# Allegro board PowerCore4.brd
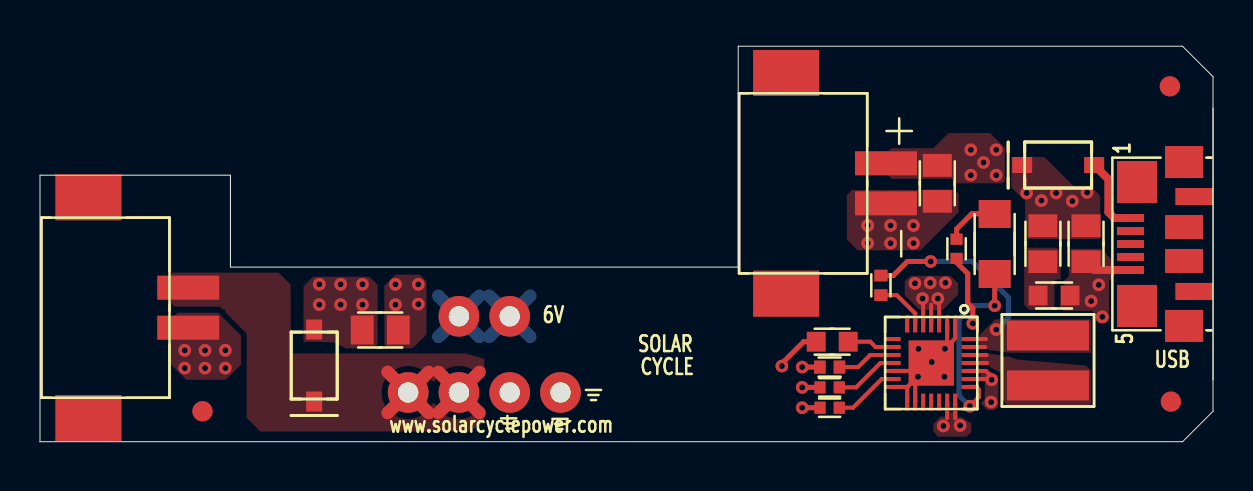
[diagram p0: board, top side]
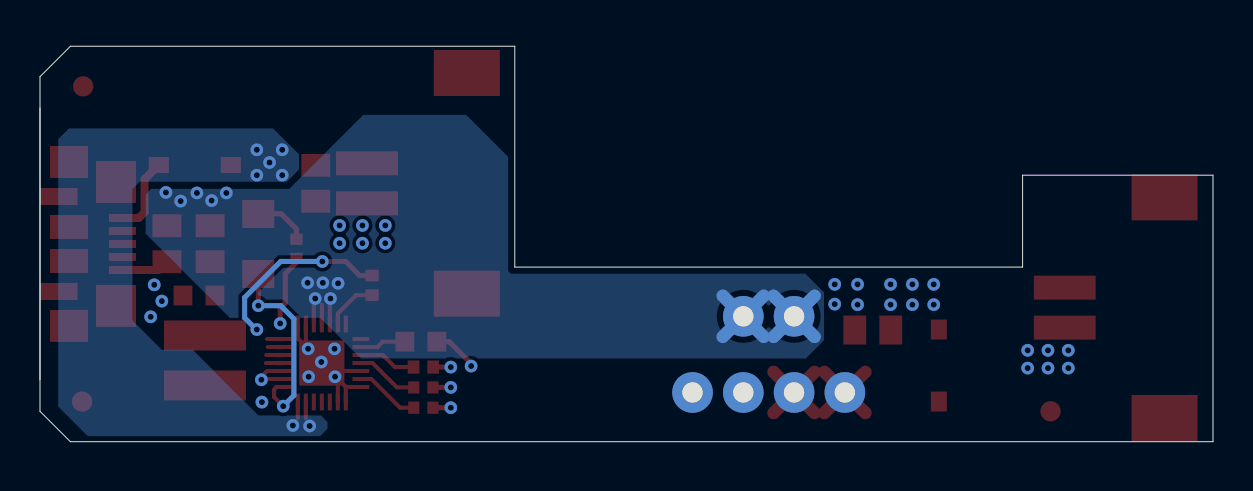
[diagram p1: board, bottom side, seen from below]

Outline 58.67 x 19.79 mm; copper layers: TOP, LAYER2_GND, LAYER3_PWR, BOTTOM. Coordinates in mm from the lower left corner of the outline.
Outline path: 0,13.34 9.53,13.34 9.53,8.74 34.92,8.74 34.92,19.79 57.15,19.79 58.67,18.26 58.67,1.52 57.15,0 0,0 0,13.34

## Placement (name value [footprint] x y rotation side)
BATTERY  -  [DF3DZ_2P_2H]  42.32 12.93 90 top
C1  2.2uF  [CAPC2013X145AN]  52.32 9.91 90 top
C3A  10uF  [CAPC2013X145AN]  44.88 12.93 270 top
C4  22uF  [CAPC2013X145AN]  17.02 5.59 0 top
C5  -  [CAPC1005X60N]  39.5 3.73 180 top
C6  -  [CAPC1608X95N]  39.62 5 180 top
C7  -  [CAPC1005X60N]  42.06 7.82 90 top
C10  4.7uF  [CAPC2013X145AN]  50.16 9.91 90 top
GND2  -  [2HOLE]  23.5 2.46 0 top
IN6V  -  [ZX62R-B-5P]  54.53 9.89 90 top
IN6V2  -  [2HOLE]  20.95 6.27 0 top
L1  -  [DEA401XCK]  50.42 4.06 90 top
LED  -  [DSAH3780]  47.75 9.89 90 top
NOREF  -  [unnamed]  8.13 1.52 0 top
NOREF#2  -  [unnamed]  56.52 17.78 0 top
NOREF#3  -  [#2]  0 0 0 top
NOREF#4  -  [#2]  9.53 13.34 0 top
NOREF#5  -  [#2]  0 13.34 0 top
NOREF#6  -  [#2]  34.92 19.79 0 top
NOREF#7  -  [#2]  0 0 0 top
NOREF#8  -  [unnamed]  56.57 2.01 0 top
NOREF#9  -  [#2]  -317.04 -262.41 0 top
NOREF#10  -  [#2]  58.67 1.52 0 top
NOREF#11  -  [#2]  57.97 18.97 0 top
NOREF#12  -  [#2]  57.15 19.79 0 top
NOREF#13  -  [#2]  32.69 -71.68 0 top
NOREF#14  -  [#2]  521.16 -249.71 0 top
NOREF#15  -  [#2]  34.92 8.74 0 top
R3  2.2K  [RESC1005X40]  45.85 9.65 270 top
R7  3.01K  [RESC1005X40]  39.5 2.72 0 top
R11  604  [RESC1005X40]  39.5 1.7 0 top
R15  -  [RESC1608X50AN]  50.72 7.32 180 top
SD1  -  [PMEG3020ER]  13.72 3.81 90 top
SD2  -  [PMEG3020ER]  50.93 13.84 0 top
SYSOUT  -  [DF3DZ_2P_2H]  7.42 6.71 90 top
SYSOUT2  -  [2HOLE]  18.41 2.46 0 top
U1  -  [QFN40P400X400X80-29AN]  44.58 3.94 270 top

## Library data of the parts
BATTERY SYSOUT = DF3DZ_2P_2H
C1 C3A C4 C10 = C0805
C5 C7 = C0402
C6 = C0603
GND2 IN6V2 SYSOUT2 = 2HOLE
IN6V = ZX62R-B-5P
L1 = DEA401XCK
LED = APL3015ZGC
R3 R7 R11 = R0402
R15 = R0603
SD1 SD2 = SCHOTTKY
U1 = MAX8903G

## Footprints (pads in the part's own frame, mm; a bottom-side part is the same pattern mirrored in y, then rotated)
2HOLE
  round 2.032 hole 1.016: 1(0,0) 2(2.54,0)
CAPC1005X60N
  rect 0.584x0.66 smd: 1(-0.49,0) 2(0.49,0)
CAPC1608X95N
  rect 0.94x0.991 smd: 1(-0.8,0) 2(0.8,0)
CAPC2013X145AN
  rect 1.143x1.448 smd: 1(-0.899,0) 2(0.899,0)
DEA401XCK
  rect 1.501x4.1 smd: 1(1.25,0) 2(-1.25,0)
DF3DZ_2P_2H
  rect 2.301x3.299 smd: (-5.522,4.994) (5.522,4.994)
  rect 1.199x3.099 smd: 1(1.001,0) 2(-1.001,0)
DSAH3780
  rect 1.4x1.6 smd: 1(-1.501,0) 2(1.501,0)
PMEG3020ER
  rect 1.001x0.8 smd: 1(1.801,0) 2(-1.801,0)
QFN40P400X400X80-29AN
  rect 0.838x0.203 smd: 1(-1.951,1.199) 2(-1.951,0.8) 3(-1.951,0.399) 4(-1.951,0) 5(-1.951,-0.399) 6(-1.951,-0.8) 7(-1.951,-1.199) 15(1.951,-1.199) 16(1.951,-0.8) 17(1.951,-0.399) 18(1.951,0) 19(1.951,0.399) 20(1.951,0.8) 21(1.951,1.199)
  rect 0.203x0.838 smd: 8(-1.199,-1.951) 9(-0.8,-1.951) 10(-0.399,-1.951) 11(0,-1.951) 12(0.399,-1.951) 13(0.8,-1.951) 14(1.199,-1.951) 22(1.199,1.951) 23(0.8,1.951) 24(0.399,1.951) 25(0,1.951) 26(-0.399,1.951) 27(-0.8,1.951) 28(-1.199,1.951)
  rect 2.261x2.261 smd: 29(0,0)
RESC1005X40
  rect 0.559x0.61 smd: 1(-0.48,0) 2(0.48,0)
RESC1608X50AN
  rect 0.94x0.991 smd: 1(-0.8,0) 2(0.8,0)
unnamed
  round 1.016 smd: (0,0)
ZX62R-B-5P
  rect 1.6x1.9 smd: (-4.1,-2.695) (4.1,-2.695)
  rect 2.101x1.999 smd: (-3.099,-0.345) (3.099,-0.345)
  rect 0.851x1.88 smd: (-2.375,-3.205) (2.375,-3.205)
  rect 1.199x1.9 smd: (-0.851,-2.695) (0.851,-2.695)
  rect 0.399x1.349 smd: 1(1.3,-0.02) 2(0.65,-0.02) 3(0,-0.02) 4(-0.65,-0.02) 5(-1.3,-0.02)

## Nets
GND2: BATTERY.2 C1.1 C3A.2 C4.2 C5.2 C6.2 GND2.1(TP-1) GND2.2(TP-1) IN6V.5(TP-5) R7.1 R11.1 R15.1 SYSOUT.2 U1.1 U1.2 U1.12 U1.14 U1.15 U1.16 U1.29
BAT: BATTERY.1 C3A.1 U1.20 U1.21
BST: C7.1 U1.6
CHG: LED.1 U1.22
CS: L1.2 U1.25 U1.26
CT: C5.1 U1.10
IDC: R7.2 U1.11
IN6V: IN6V.1(TP-1) SD2.1(TP-1)
IN6V2: C1.2 C10.2 IN6V2.1(TP-1) IN6V2.2(TP-1) SD2.2(TP-2) U1.3 U1.4 U1.5
ISET: R11.2 U1.13
LX: C7.2 L1.1 U1.27 U1.28
N0001: C10.1 R15.2
N0002: LED.2 R3.1
SYS: C4.1 R3.2 SD1.1(TP-1) U1.23 U1.24
SYSOUT2: SD1.2(TP-2) SYSOUT.1 SYSOUT2.1(TP-1) SYSOUT2.2(TP-1)
VL: C6.1 U1.9

Pads without a net: IN6V 2 3 4; U1 7 8 17 18 19

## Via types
v1: diameter 0.635, hole 0.305, TOP to BOTTOM, 58 vias

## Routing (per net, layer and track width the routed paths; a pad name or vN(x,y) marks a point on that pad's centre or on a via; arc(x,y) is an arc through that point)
GND2: length 28.4
  TOP w0.203: v1(43.92,3.25) 43.63,3.54 U1.12 ; U1.15 43.38,2.74 ; 43.38,2.74 43.78,3.14 ; 43.38,2.74 U1.14 ; U1.1 45.78,5.16 v1(45.26,4.65) ; U1.2 45.38,4.74 U1.29 43.78,3.14 ; 43.78,3.14 U1.16
  TOP w0.254: R7.1 v1(38.13,2.72) ; 52.74,8.59 C1.1 ; C6.2 38.2,5 37.11,3.91 v1(37.11,3.78) ; C5.2 v1(38.13,3.73) ; R11.1 v1(38.13,1.7)
  TOP w0.399: IN6V.5 52.74,8.59
  LAYER2_GND w0.635: 22.47,3.49 GND2.1 ; GND2.1 22.47,1.44 ; GND2.1 24.52,1.44 ; GND2.1 24.52,3.49 ; 25.01,3.49 GND2.2 ; GND2.2 27.06,3.49 ; GND2.2 25.01,1.44 ; GND2.2 27.06,1.44
  vias: v1(7.24,4.57) v1(7.24,3.68) v1(8.26,4.57) v1(8.26,3.68) v1(9.27,4.57) v1(9.27,3.68) v1(17.78,7.87) v1(17.78,6.86) v1(18.92,7.87) v1(18.92,6.88) v1(41.4,10.82) v1(41.4,9.93) v1(42.55,10.82) v1(42.55,9.93) v1(43.69,10.82) v1(43.69,9.93) v1(43.94,4.65) v1(44.6,3.99) v1(45.24,3.25) v1(52.58,7.04) v1(52.96,7.85) v1(53.14,6.25)
BAT: length 1.6
  TOP w0.203: U1.21 45.78,1.17 ; U1.20 45.38,1.18
  vias: v1(45.19,0.79) v1(46.02,0.81) v1(46.56,14.61) v1(46.56,13.34) v1(47.19,13.97) v1(47.83,14.61) v1(47.83,13.34)
BST: length 2.6
  TOP w0.203: U1.6 43.78,6.41 42.86,7.33 C7.1
CHG: length 9.7
  TOP w0.203: U1.22 46.84,2.74 46.96,2.61 46.96,2.24 v1(46.51,1.78)
  TOP w0.254: LED.1 v1(47.75,6.81)
  BOTTOM w0.254: v1(46.51,1.78) 45.97,2.31 45.97,6.15 46.63,6.81 v1(47.75,6.81)
CS: length 1.7
  TOP w0.203: U1.26 47.35,4.34 ; U1.25 47.37,3.94
CT: length 2.9
  TOP w0.203: U1.10 41.52,4.34 40.92,3.73 C5.1
IDC: length 3.2
  TOP w0.203: U1.11 42.04,3.94 40.82,2.72 R7.2
IN6V: length 3.9
  TOP w0.399: IN6V.1 53.73,11.19 53.44,11.48 53.44,13.13 SD2.1
IN6V2: length 14.5
  TOP w0.203: U1.3 44.98,6.87 ; U1.4 44.58,6.86 ; U1.5 44.18,6.82
  BOTTOM w0.635: 19.93,7.3 IN6V2.1 ; IN6V2.1 21.98,5.25 ; IN6V2.1 21.98,7.3 ; IN6V2.1 19.93,5.25 ; 22.47,5.25 23.5,6.27 ; 23.5,6.27 24.52,7.3 ; 23.5,6.27 22.47,7.3 ; 23.5,6.27 24.52,5.25
  vias: v1(43.76,7.92) v1(44.15,7.16) v1(44.53,7.95) v1(44.91,7.16) v1(45.29,7.95) v1(49.35,12.45) v1(50.09,12.06) v1(50.83,12.45) v1(51.64,12.04) v1(52.37,12.47)
ISET: length 3.2
  TOP w0.203: R11.2 40.67,1.7 42.1,3.14 U1.13
LX: length 10.8
  TOP w0.203: U1.27 47.28,4.74 ; U1.28 47.32,5.14
  TOP w0.254: v1(44.55,9.02) 43.38,9.02 42.68,8.31 C7.2
  BOTTOM w0.254: v1(47.83,5.61) 47.85,5.61 48.44,6.2 48.44,7.21 46.63,9.02 v1(44.55,9.02)
N0002: length 2.7
  TOP w0.254: R3.1 45.85,10.64 46.61,11.4 47.74,11.4 LED.2
SYS: length 6.1
  TOP w0.203: U1.24 47.31,3.54 47.68,3.17 47.64,3.14 U1.23
  TOP w0.254: v1(46.66,5.92) 46.66,6.68 46.41,6.93 46.41,8.41 45.85,8.97 R3.2
  vias: v1(13.97,7.87) v1(13.97,6.86) v1(15.04,7.87) v1(15.04,6.86) v1(16.13,7.87) v1(16.13,6.86) v1(47.6,3.1) v1(47.57,1.98)
SYSOUT2: length 11.6
  TOP w0.635: SYSOUT2.2 21.98,3.49 ; SYSOUT2.2 19.93,1.44 ; SYSOUT2.2 19.93,3.49 ; SYSOUT2.2 21.98,1.44 ; SYSOUT2.1 19.44,3.49 ; SYSOUT2.1 17.39,3.49 ; SYSOUT2.1 17.39,1.44 ; SYSOUT2.1 19.44,1.44
VL: length 2.3
  TOP w0.203: C6.1 41.53,5 41.8,4.74 U1.9

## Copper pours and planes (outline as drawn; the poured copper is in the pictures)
GND2 on TOP: 51.59,9.65 51.46,9.53 51.46,8.28 50.95,7.77 50.95,6.78 51.18,6.55 52.6,6.55 52.81,6.35 52.81,6.07 52.96,5.92 53.31,5.92 53.47,6.07 53.47,8.05 53.82,8.41 54.81,8.41 54.81,8.79 53.82,8.79 53.82,8.89 53.06,9.65
GND2 on TOP: 17.42,4.67 18.64,4.67 19.33,5.36 19.33,8.03 19,8.36 17.78,8.36 17.22,7.8 17.22,4.88
GND2 on TOP: 45.75,12.6 45.95,12.4 45.95,11.48 44.04,9.58 40.89,9.58 40.36,10.11 40.36,12.34 40.61,12.6
GND2 on TOP: 8.92,6.45 6.88,6.45 6.53,6.1 6.53,3.89 7.32,3.1 9.3,3.1 10.06,3.86 10.06,5.31
GND2 on LAYER2_GND: 57.03,0.28 0.28,0.28 0.28,13.06 9.25,13.06 9.25,8.46 35.2,8.46 35.2,19.51 57.03,19.51 58.39,18.15 58.39,1.64
BAT on TOP: 45.24,1.24 45.03,1.24 44.68,0.89 44.68,0.56 44.89,0.25 46.35,0.25 46.58,0.48 46.58,0.93 46.05,1.24 45.92,1.24 45.9,1.47 45.24,1.47
BAT on TOP: 42.57,14.68 44.68,14.68 45.44,15.44 47.52,15.44 48.26,14.71 48.26,13.06 48.13,12.93 45.82,12.93 45.59,13.16 42.6,13.16 42.24,13.51 42.24,14.35
BAT on BOTTOM: 44.65,0.28 44.3,0.64 44.3,0.99 44.63,1.32 47.75,1.32 51.03,4.6 52.58,4.6 54.05,6.07 54.05,12.65 53.72,12.98 53.75,13 46.33,13 45.72,13.61 45.72,14.38 47.02,15.67 57.23,15.67 57.76,15.14 57.76,1.75 56.29,0.28
CS on TOP: 46.99,4.47 48.02,4.47 48.84,4.11 52.32,3.81 52.58,3.56 52.58,1.91 52.45,1.78 48.39,1.78 48.13,2.12 48.13,3.4 47.37,3.81 46.99,3.81
IN6V2 on TOP: 53.04,10.14 53.01,10.13 49.35,10.13 49.28,10.21 49.28,12.04 48.59,12.73 48.59,14.25 50.24,14.25 51.69,12.8 52.53,12.8 53.04,12.29
IN6V2 on TOP: 45.16,6.6 45.92,7.37 45.92,7.92 45.54,8.31 43.54,8.31 43.26,8.03 43.26,7.26 43.92,6.6
IN6V2 on BOTTOM: 42.62,4.17 20.37,4.17 19.46,5.08 19.46,7.47 20.4,8.41 35.13,8.41 35.26,8.53 35.26,14.25 37.36,16.36 42.49,16.36 46.2,12.65 53.11,12.65 53.39,12.37 53.39,10.41 49.17,6.2 44.65,6.2
LX on TOP: 46.99,5.33 47.78,6.12 52.53,6.12 52.58,6.07 52.58,4.45 48.51,4.45 47.42,4.6 46.99,4.6
N0001 on TOP: 49.38,9.7 50.85,9.7 51.05,9.5 51.05,7.09 50.57,6.6 49.48,6.6 49.23,6.86 49.23,9.55
SYS on TOP: 13.18,5 13.18,7.77 13.67,8.26 16.48,8.26 16.89,7.85 16.89,4.9 16.71,4.67 15.29,4.67 14.68,4.98
SYS on TOP: 47.04,1.93 47.4,1.57 47.73,1.57 47.93,1.72 47.93,3.51 47.73,3.71 47.04,3.71
SYS on LAYER3_PWR: 46.58,6.68 48.56,4.7 48.56,1.24 47.68,0.36 12.6,0.36 11.79,1.17 11.79,7.87 12.19,8.28 42.57,8.28 44.17,6.68
SYSOUT2 on TOP: 21.26,4.42 22.23,4.15 22.23,0.99 21.46,0.51 11.02,0.51 10.34,1.19 10.34,5.41 8.99,6.76 6.73,6.76 6.27,7.21 6.27,8.13 6.6,8.46 11.94,8.46 12.54,7.86 12.55,4.42

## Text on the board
BOTTOM: SOLDER SIDE ETCH | 4
Ref Des/Silkscreen Bottom: BOTTOM SILKSCREEN | 4
User.Comments: SOLARCYCLE
Ref Des/Silkscreen Top: www.solarcyclepower.com | 6V | SOLAR | CYCLE | USB | TOP SILKSCREEN | 5
LAYER2_GND: LAYER 2 GND PLANE | 2
LAYER3_PWR: LAYER 3 GND PLANE | 3
BODY_CENTER: (408) 582-2787  johnc@cdspcb.com | CORCORAN DESIGN SERVICE,INC | SOLARCYCLE
DISPLAY_TOP: PASTEMASK BOTTOM | 10
User.11: NOTES (UNLESS OTHERWISE SPECIFIED): | SOLDERED ENTITY. | 4.   SOLDER MASK BOTH SIDES WITH LIQUID PHOTO IMAGEABLE SOLDER MASK (LPI), GREEN. | 5.   SILKSCREEN TOP SIDE WITH WHITE EPOXY NON CONDUCTIVE INK.  SILKSCREEN MAY BE TRIMMED OFF ANY | 2.   NUMBER OF LAYERS: 4 | 3.   FINISH: HOT AIR SOLDER LEVELED (HASL) | 1.   MATERIAL : FR-4 | 2X | NOTE: NOMINAL THICKNESS = 40 MILS (+/-10%) | STACKUP | DETAIL `A'
User.12: NOTES (UNLESS OTHERWISE SPECIFIED): | 1.  Workmanship standards and acceptability criteria shall meet | IPC-A-610 (latest revision). | 10/1 | SYSOUT2 | IN6V2 | GND2 | L1 | C4 | COMPONENT SIDE | C5 | R7 | R11 | C7 | C6 | U1 | R3 | C10 | R15 | SD2 | C1 | SYSOUT | BATTERY | SD1 | C3A | LED | IN6V
User.14: SILKSCREEN TOP | SOLDER MASK TOP | LAYER 1  - TOP ETCH  - 2  OZ. | LAYER 2  - GND PLANE - 2  OZ. | LAYER 3  - GND PLANE/ SIG - 2  OZ. | LAYER 4  - BOTTOM ETCH - 2  OZ. | SOLDERMASK BOTTOM | SILKSCREEN BOTTOM | PREPREG | CORE | .040"+/-.10% | (NOM)
User.16: FIGURE | SIZE | 12.0 | 40.0 | DRILL CHART: TOP to BOTTOM | ALL UNITS ARE IN MILS | TOLERANCE | +0.0/-12.0 | +3.0/-3.0 | PLATED | QTY | 58 | 6
